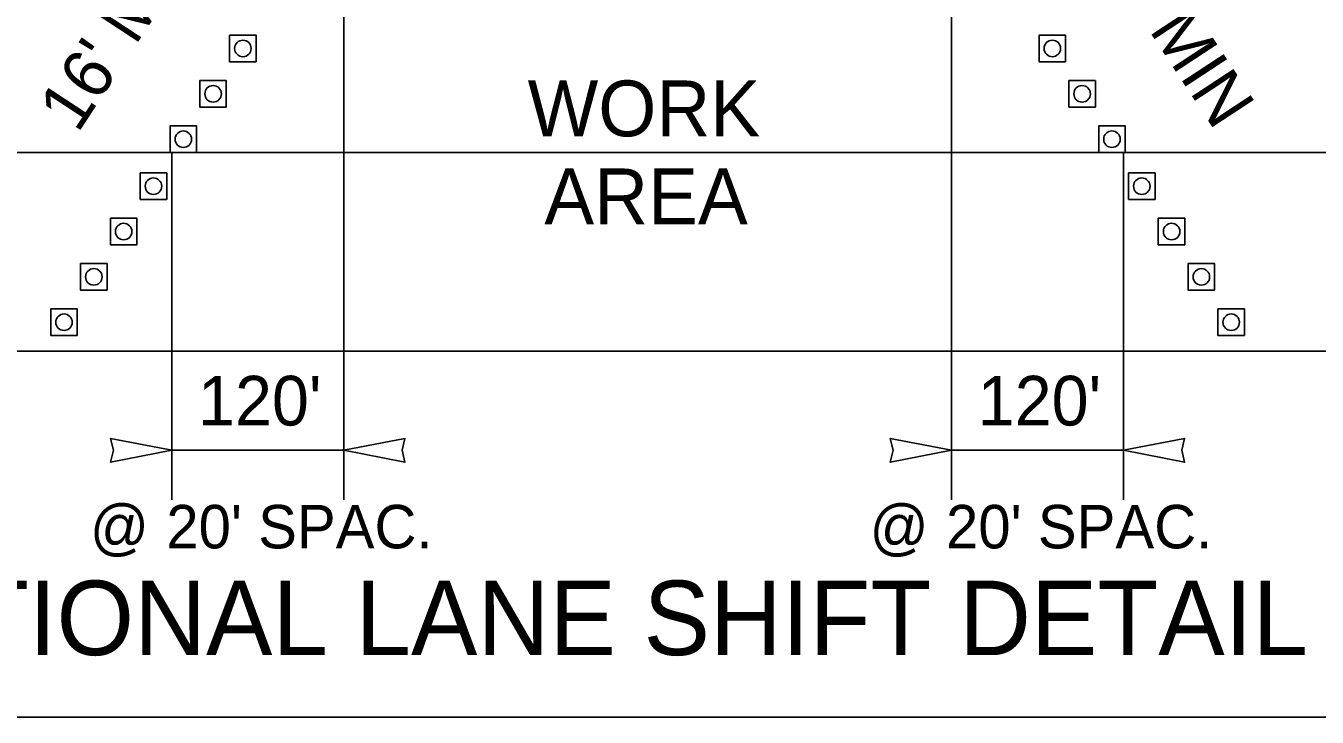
# Model space of a CAD drawing. Extents: x 99999.1 to 100095.7, y 99995 to 100010.7.
# Drawn here: x 100006.052 to 100008.131, y 100003.475 to 100004.589 of the extents above; entities that cross this region are included whole.
import ezdxf

# ---------------------------------------------------------------- set-up
doc = ezdxf.new("R2010")
doc.units = 0
for name, color, linetype in [('RD_ED_ShoulderPavedEdge', 7, 'Continuous'), ('RD_MK_LineEdgeWhite', 7, 'Continuous'), ('SH_DE_DetailHeading2Text', 7, 'Continuous'), ('SH_TI_Tables', 7, 'Continuous'), ('TR_WZ_TrafficCone', 7, 'Continuous'), ('TR_WZ_WorkZoneDetails', 7, 'Continuous'), ('TR_WZ_WorkZoneTextCurrent', 7, 'Continuous')]:
    doc.layers.add(name, color=color, linetype=linetype)

msp = doc.modelspace()

# ---------------------------------------------------------------- linework, layer by layer
at = {"layer": 'RD_ED_ShoulderPavedEdge'}
msp.add_line((100005.1009, 100004.0655), (100009.0183, 100004.0655), dxfattribs=at)
at = {"layer": 'RD_MK_LineEdgeWhite'}
msp.add_line((100005.1009, 100004.3855), (100009.0183, 100004.3855), dxfattribs=at)
at = {"layer": 'SH_TI_Tables'}
msp.add_lwpolyline([(100004.9869, 100005.5662), (100009.1323, 100005.5662), (100009.1323, 100003.4755), (100004.9869, 100003.4755)], close=True, dxfattribs=at)
at = {"layer": 'TR_WZ_TrafficCone'}
for points in [[(100006.3799, 100004.5316), (100006.4226, 100004.5316), (100006.4226, 100004.5743), (100006.3799, 100004.5743), (100006.3799, 100004.5316)], [(100006.3799, 100004.5743), (100006.4226, 100004.5743), (100006.4226, 100004.5316), (100006.3799, 100004.5316), (100006.3799, 100004.5743)], [(100007.7263, 100004.5316), (100007.6836, 100004.5316), (100007.6836, 100004.5743), (100007.7263, 100004.5743), (100007.7263, 100004.5316)], [(100007.7263, 100004.5743), (100007.6836, 100004.5743), (100007.6836, 100004.5316), (100007.7263, 100004.5316), (100007.7263, 100004.5743)], [(100006.3319, 100004.4586), (100006.3746, 100004.4586), (100006.3746, 100004.5012), (100006.3319, 100004.5012), (100006.3319, 100004.4586)], [(100006.3319, 100004.5012), (100006.3746, 100004.5012), (100006.3746, 100004.4586), (100006.3319, 100004.4586), (100006.3319, 100004.5012)], [(100007.7743, 100004.4586), (100007.7316, 100004.4586), (100007.7316, 100004.5012), (100007.7743, 100004.5012), (100007.7743, 100004.4586)], [(100007.7743, 100004.5012), (100007.7316, 100004.5012), (100007.7316, 100004.4586), (100007.7743, 100004.4586), (100007.7743, 100004.5012)], [(100006.2839, 100004.3855), (100006.3266, 100004.3855), (100006.3266, 100004.4282), (100006.2839, 100004.4282), (100006.2839, 100004.3855)], [(100006.2839, 100004.4282), (100006.3266, 100004.4282), (100006.3266, 100004.3855), (100006.2839, 100004.3855), (100006.2839, 100004.4282)], [(100007.8223, 100004.3855), (100007.7796, 100004.3855), (100007.7796, 100004.4282), (100007.8223, 100004.4282), (100007.8223, 100004.3855)], [(100007.8223, 100004.4282), (100007.7796, 100004.4282), (100007.7796, 100004.3855), (100007.8223, 100004.3855), (100007.8223, 100004.4282)], [(100006.2359, 100004.3524), (100006.2786, 100004.3524), (100006.2786, 100004.3098), (100006.2359, 100004.3098), (100006.2359, 100004.3524)], [(100006.2359, 100004.3098), (100006.2786, 100004.3098), (100006.2786, 100004.3524), (100006.2359, 100004.3524), (100006.2359, 100004.3098)], [(100007.8276, 100004.3524), (100007.8703, 100004.3524), (100007.8703, 100004.3098), (100007.8276, 100004.3098), (100007.8276, 100004.3524)], [(100007.8276, 100004.3098), (100007.8703, 100004.3098), (100007.8703, 100004.3524), (100007.8276, 100004.3524), (100007.8276, 100004.3098)], [(100006.1879, 100004.2794), (100006.2306, 100004.2794), (100006.2306, 100004.2367), (100006.1879, 100004.2367), (100006.1879, 100004.2794)], [(100006.1879, 100004.2367), (100006.2306, 100004.2367), (100006.2306, 100004.2794), (100006.1879, 100004.2794), (100006.1879, 100004.2367)], [(100007.8756, 100004.2794), (100007.9183, 100004.2794), (100007.9183, 100004.2367), (100007.8756, 100004.2367), (100007.8756, 100004.2794)], [(100007.8756, 100004.2367), (100007.9183, 100004.2367), (100007.9183, 100004.2794), (100007.8756, 100004.2794), (100007.8756, 100004.2367)], [(100006.1399, 100004.2063), (100006.1826, 100004.2063), (100006.1826, 100004.1636), (100006.1399, 100004.1636), (100006.1399, 100004.2063)], [(100006.1399, 100004.1636), (100006.1826, 100004.1636), (100006.1826, 100004.2063), (100006.1399, 100004.2063), (100006.1399, 100004.1636)], [(100007.9236, 100004.2063), (100007.9663, 100004.2063), (100007.9663, 100004.1636), (100007.9236, 100004.1636), (100007.9236, 100004.2063)], [(100007.9236, 100004.1636), (100007.9663, 100004.1636), (100007.9663, 100004.2063), (100007.9236, 100004.2063), (100007.9236, 100004.1636)], [(100006.0919, 100004.1332), (100006.1346, 100004.1332), (100006.1346, 100004.0906), (100006.0919, 100004.0906), (100006.0919, 100004.1332)], [(100006.0919, 100004.0906), (100006.1346, 100004.0906), (100006.1346, 100004.1332), (100006.0919, 100004.1332), (100006.0919, 100004.0906)], [(100007.9716, 100004.1332), (100008.0143, 100004.1332), (100008.0143, 100004.0906), (100007.9716, 100004.0906), (100007.9716, 100004.1332)], [(100007.9716, 100004.0906), (100008.0143, 100004.0906), (100008.0143, 100004.1332), (100007.9716, 100004.1332), (100007.9716, 100004.0906)]]:
    msp.add_lwpolyline(points, dxfattribs=at)
for centre in [(100006.4013, 100004.553), (100007.7049, 100004.553), (100006.3533, 100004.4799), (100007.7529, 100004.4799), (100006.3053, 100004.4068), (100007.8009, 100004.4068), (100006.2572, 100004.3311), (100007.849, 100004.3311), (100006.2092, 100004.258), (100007.897, 100004.258), (100006.1612, 100004.185), (100007.945, 100004.185), (100006.1132, 100004.1119), (100007.993, 100004.1119)]:
    msp.add_circle(centre, 0.0133, dxfattribs=at)
at = {"layer": 'TR_WZ_WorkZoneDetails'}
for p, q in [((100006.2866, 100004.3855), (100006.2866, 100003.8255)), ((100007.8196, 100004.3855), (100007.8196, 100003.8255)), ((100006.5639, 100004.0655), (100006.5639, 100003.8255)), ((100007.5423, 100004.0655), (100007.5423, 100003.8255)), ((100006.2866, 100003.9055), (100006.5639, 100003.9055)), ((100007.5423, 100003.9055), (100007.8196, 100003.9055))]:
    msp.add_line(p, q, dxfattribs=at)
for points in [[(100006.5639, 100004.7828), (100006.5639, 100004.0655), (100007.5423, 100004.0655), (100007.5423, 100004.7828)], [(100006.2866, 100003.9055), (100006.1883, 100003.9248), (100006.1928, 100003.9055), (100006.1883, 100003.8862)], [(100006.5639, 100003.9055), (100006.6622, 100003.9248), (100006.6576, 100003.9055), (100006.6622, 100003.8862)], [(100007.5423, 100003.9055), (100007.444, 100003.9248), (100007.4486, 100003.9055), (100007.444, 100003.8862)], [(100007.8196, 100003.9055), (100007.9179, 100003.9248), (100007.9134, 100003.9055), (100007.9179, 100003.8862)]]:
    msp.add_lwpolyline(points, close=True, dxfattribs=at)

# ---------------------------------------------------------------- texts
at = {"layer": 'SH_DE_DetailHeading2Text'}
msp.add_text('OPTIONAL LANE SHIFT DETAIL', height=0.12, rotation=360, dxfattribs=at).set_placement((100005.7267, 100003.5755))
at = {"layer": 'TR_WZ_WorkZoneDetails'}
for s, p in [('WORK', (100006.86, 100004.4114)), ('AREA', (100006.8867, 100004.2696))]:
    msp.add_text(s, height=0.09, dxfattribs=at).set_placement(p)
at = {"layer": 'TR_WZ_WorkZoneTextCurrent'}
for s, height, rotation, p in [("16' MIN", 0.08, 56.6977, (100006.1351, 100004.415)), ("16' MIN", 0.08, 303.3023, (100007.7668, 100004.7241)), ("120'", 0.08, 360, (100006.3291, 100003.9455)), ("120'", 0.08, 360, (100007.5848, 100003.9455)), ('@', 0.07, 360, (100006.155, 100003.7475)), ("20' SPAC.", 0.07, 360, (100006.2779, 100003.7475)), ('@', 0.07, 360, (100007.4107, 100003.7475)), ("20' SPAC.", 0.07, 360, (100007.5336, 100003.7475))]:
    msp.add_text(s, height=height, rotation=rotation, dxfattribs=at).set_placement(p)

doc.saveas('drawing.dxf')
